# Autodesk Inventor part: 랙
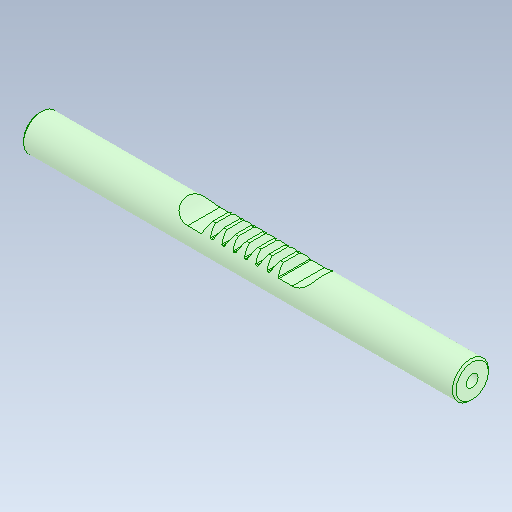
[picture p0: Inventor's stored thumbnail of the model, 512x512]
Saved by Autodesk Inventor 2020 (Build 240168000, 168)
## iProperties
Created: 2024-07
Part Number: 랙
Material: 강철, 탄소
Document SubType Name: Modeling
Designer: oem
Density: 7.85 g/cm^3
Appearance: 기본값
Mass: 555.229 g
Surface Area: 168.573 cm^2
Volume: 70.7298 cm^3
Sending System: Autodesk Inventor 2025
Preprocessor: ST-DEVELOPER v20
Author: jhkim
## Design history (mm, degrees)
feature "솔리드1"
node "솔리드2"
